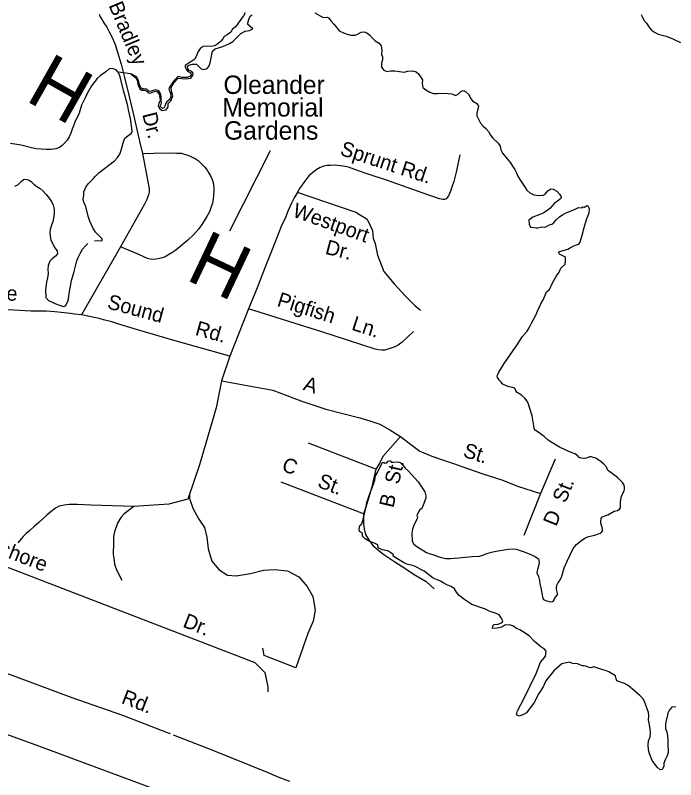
# Model space of a CAD drawing. Extents: x 1945482 to 2853149, y 66427 to 1015778.
# Drawn here: x 2352907 to 2355850, y 165984 to 169389 of the extents above; entities that cross this region are included whole.
import ezdxf

# ---------------------------------------------------------------- set-up
doc = ezdxf.new("R2010")
doc.units = 0
for name, color, linetype in [('Old_Level_10', 7, 'Continuous'), ('Old_Level_22', 7, 'Continuous'), ('Old_Level_35', 7, 'Continuous'), ('Old_Level_60', 7, 'Continuous')]:
    doc.layers.add(name, color=color, linetype=linetype)

msp = doc.modelspace()

# ---------------------------------------------------------------- linework, layer by layer
at = {"layer": 'Old_Level_22'}
msp.add_lwpolyline([(2354042.6, 168785.4), (2353861.4, 168427.5)], dxfattribs=at)
at = {"layer": 'Old_Level_35'}
for p, q in [((2353375.3, 168357.6), (2353201.2, 168054.7)), ((2353862.9, 167870.5), (2353825, 167761.2)), ((2354514.2, 167367.1), (2354213.3, 167482.8)), ((2355312.1, 167411.8), (2355247.9, 167258.2)), ((2355247.9, 167258.2), (2355172.6, 167071.1))]:
    msp.add_line(p, q, dxfattribs=at)
for points in [[(2353280.4, 169394.3), (2353284.8, 169382.3), (2353293.2, 169368.5), (2353302, 169355.1), (2353314.5, 169335.6), (2353325.5, 169316), (2353338.3, 169290.6), (2353351.7, 169258.9), (2353362.9, 169225.2), (2353379.1, 169172), (2353393.6, 169112.6), (2353412.5, 169033.2), (2353434, 168946.1), (2353460.6, 168829), (2353473, 168773.7)], [(2353473, 168773.7), (2353522.8, 168775.7), (2353598.9, 168776.4), (2353626.9, 168775.5), (2353646.9, 168774.4), (2353659.2, 168770.9), (2353675.5, 168765.6), (2353685.5, 168762.1), (2353697.9, 168756.3), (2353707.9, 168750.8), (2353722.4, 168741.6), (2353736.7, 168728), (2353751.5, 168712.5), (2353762.2, 168698.8), (2353768.5, 168689.2), (2353777, 168673.5), (2353783.8, 168657.7), (2353788.3, 168644.1), (2353791.1, 168622.2), (2353791.7, 168608.1), (2353790.7, 168584.1), (2353785.7, 168551.7), (2353776.8, 168527.4), (2353771.5, 168513.1), (2353760.1, 168493), (2353741.3, 168462), (2353724.3, 168437.4), (2353701.4, 168410.6), (2353676.4, 168387.6), (2353649.4, 168364.5), (2353622, 168343.4), (2353604.4, 168330.6), (2353586.8, 168320), (2353575.3, 168313.3), (2353563.3, 168308.9), (2353541.5, 168304.1), (2353525.5, 168301.5), (2353509.7, 168302.9), (2353495.5, 168306.2), (2353483.1, 168311.6), (2353456.7, 168322.8), (2353375.3, 168357.6)], [(2353473, 168773.7), (2353490.8, 168680.2), (2353503.2, 168616.7), (2353503.7, 168604.6), (2353503.8, 168600.6), (2353500.3, 168588.7), (2353491.1, 168566.3), (2353481.9, 168547.9), (2353375.3, 168357.6)], [(2354887.8, 168767.7), (2354870.9, 168690.9), (2354860.4, 168648.4), (2354850.4, 168618.8), (2354846, 168605.9), (2354837, 168585.5), (2354827.4, 168571), (2354819.6, 168568.7), (2354811.7, 168568.4), (2354797.5, 168571.8), (2354720.2, 168598.9), (2354566.1, 168652.9), (2354479, 168681.3), (2354436.4, 168695.7), (2354391.8, 168711.9), (2354367.7, 168716.9), (2354341.3, 168719.8), (2354327.5, 168721.2), (2354311.4, 168720.6), (2354297.3, 168720), (2354281.7, 168717.4), (2354265.8, 168710.9), (2354248.2, 168700.4), (2354230.7, 168687.5), (2354217, 168674.8), (2354199.8, 168654.1), (2354184.9, 168633.5), (2354173.4, 168617.3), (2354162.3, 168598.8), (2354149.1, 168576.3), (2354137.9, 168551.9), (2354123.4, 168519.2), (2354110.5, 168488.8), (2354092.1, 168448), (2354061.1, 168368.7), (2354024.6, 168279.3), (2353984.7, 168175.6), (2353946.4, 168081.9), (2353901.1, 167968.1), (2353862.9, 167870.5)], [(2354163.5, 168600.8), (2354424.1, 168512.5), (2354474.8, 168481.3), (2354498.2, 168430.6), (2354502.1, 168395.5), (2354509.9, 168372.1), (2354521.6, 168321.3), (2354548.9, 168247.2), (2354595.7, 168192.6), (2354646.3, 168138), (2354689.2, 168095.1), (2354712.6, 168075.6)], [(2353862.9, 167870.5), (2353619.9, 167939), (2353451.9, 167988.4), (2353368.9, 168013), (2353336.6, 168023.9), (2353300.2, 168032.3), (2353279.9, 168037.8), (2353257.8, 168042.8), (2353237.5, 168047.9), (2353201.2, 168054.7), (2353171.2, 168057.4), (2353153, 168060.6), (2353110.8, 168064.9), (2353082.8, 168067.7), (2353064.7, 168069.3), (2353044.6, 168070.4), (2352976.6, 168071.7), (2352848.4, 168078.4)], [(2354680.7, 167981), (2354630.8, 167933), (2354613.2, 167920.2), (2354597.5, 167911.7), (2354571.9, 167902.8), (2354554, 167897.8), (2354539.9, 167897.3), (2354526.1, 167899), (2354509.9, 167902.3), (2354272.8, 167978.9), (2353946.4, 168081.9)], [(2353825, 167761.2), (2353801.3, 167640.1), (2353728.1, 167386.6), (2353675.5, 167233.1)], [(2353825, 167761.2), (2354053.9, 167718.9), (2354179.4, 167671.4), (2354291, 167635.1), (2354366.3, 167615.6), (2354441.7, 167596), (2354486.7, 167582.4), (2354530.9, 167568.1), (2354575.6, 167543), (2354623, 167512.3)], [(2354623, 167512.3), (2354578.4, 167462), (2354544.9, 167422.9), (2354530.9, 167395), (2354514.2, 167367.1), (2354494.7, 167283.3), (2354477.9, 167227.5), (2354466.8, 167194), (2354458.8, 167167.5)], [(2354623, 167512.3), (2354667.6, 167478.8), (2354709.5, 167448.1), (2354762.5, 167425.7), (2354809.9, 167409), (2354860.1, 167392.2), (2354921.5, 167369.9), (2354994.1, 167344.8), (2355075, 167319.6), (2355144.7, 167291.7), (2355247.9, 167258.2)], [(2354458.8, 167167.5), (2354091.1, 167309.2)], [(2353683.1, 167254.2), (2353683.2, 167237.1), (2353698.6, 167194.1), (2353724.1, 167143.9), (2353749.5, 167106.7), (2353760.6, 167063.8), (2353766.9, 167012.9), (2353782.5, 166958.1), (2353814.6, 166919.2), (2353852.7, 166895.3), (2353890.8, 166892.1), (2353954.3, 166901.7), (2354013.1, 166917.6), (2354062.3, 166920.7), (2354119.5, 166914.4), (2354170.3, 166887.4), (2354206.8, 166844.5), (2354232.2, 166800), (2354243.3, 166739.6), (2354233.8, 166690.3), (2354210, 166634.7), (2354189.3, 166575.9), (2354156.5, 166482.1)], [(2353434.9, 167200.4), (2353244.8, 167207.5), (2353184.7, 167209.1), (2353146.9, 167209.5), (2353124.7, 167206.7), (2353102.9, 167201.9), (2353085.5, 167193), (2353066.1, 167178.4), (2353046.7, 167161.6), (2353031.2, 167146.9), (2353011.9, 167130), (2352990.6, 167111.4), (2352971.3, 167094.6), (2352955.8, 167079.9), (2352942.1, 167067.5), (2352917.9, 167038.6)], [(2353675.5, 167233.1), (2353591.1, 167210.7), (2353434.9, 167200.4)], [(2353434.9, 167200.4), (2353392.5, 167167.8), (2353376.8, 167151.3), (2353361.8, 167126.4), (2353356.1, 167109.3), (2353350.9, 167094.4), (2353346.1, 167075), (2353344.9, 167060.7), (2353344.2, 167042.2), (2353344, 167023), (2353342.6, 167003), (2353343.3, 166988.1), (2353346.4, 166969.3), (2353346.8, 166959.5), (2353349.4, 166943.5), (2353356.1, 166923.7), (2353362.6, 166909.9), (2353381.2, 166872)], [(2354458.8, 167167.5), (2354458.4, 167143.7), (2354458.4, 167124.2), (2354461.2, 167101.8), (2354466.8, 167076.7), (2354483.5, 167048.8), (2354500.2, 167026.5), (2354544.9, 166990.2), (2354597.9, 166953.9), (2354642.5, 166925.9), (2354684.4, 166898), (2354737.4, 166867.3), (2354773.7, 166833.8)], [(2352206.7, 166694.6), (2352263.7, 166828.2), (2352297, 166900.4), (2352338.6, 166964.3), (2352391.4, 167006), (2352452.5, 167019.9), (2352530.2, 167014.3), (2352655.2, 167000.4), (2352774.6, 166967.1), (2353974.1, 166505.9), (2354018.5, 166461.4), (2354032.4, 166397.5), (2354032.4, 166375.3)], [(2353598.4, 166187.9), (2353585, 166193.1), (2353386.1, 166269.3), (2353160.7, 166348.3), (2352908.9, 166442.4), (2352750.7, 166500.1), (2352564, 166564.6), (2352206.7, 166694.6), (2351847.3, 166826.4)], [(2351702.3, 166647.1), (2352243.1, 166411.9), (2352998.3, 166138.4)], [(2354156.5, 166482.1), (2354015.8, 166536.4), (2354010.2, 166569.8)], [(2354129.9, 165976.4), (2354101.6, 165985.5), (2354075, 165996.2), (2354030.2, 166016.4), (2353953.1, 166047.5), (2353784.4, 166114.7), (2353612.5, 166182.3)], [(2352998.3, 166138.4), (2353646.7, 165899.3)]]:
    msp.add_lwpolyline(points, dxfattribs=at)
at = {"layer": 'Old_Level_60'}
msp.add_line((2353421.2, 169128.7), (2353365.5, 169136.1), dxfattribs=at)
for points in [[(2353930.5, 169400.7), (2353923.5, 169386.2), (2353888, 169337.5), (2353874.2, 169326.7), (2353866.7, 169313.3), (2353851.5, 169302.1), (2353838, 169295.4), (2353831.2, 169284.1), (2353821.5, 169272.1), (2353809.5, 169262.4), (2353795.5, 169253.5), (2353777, 169250.3), (2353760.7, 169251.5), (2353744.2, 169250.6), (2353731, 169241.7), (2353721.5, 169228), (2353714.5, 169210.7), (2353706.5, 169194.1), (2353693.7, 169185.2), (2353677, 169175.1), (2353664.5, 169164.8), (2353663.7, 169158.8), (2353668.5, 169149.2), (2353673.5, 169140.3), (2353688.2, 169133.1), (2353691.2, 169125.1), (2353688.2, 169117.9), (2353672, 169112.1), (2353650.5, 169112.8), (2353634.2, 169117.2), (2353627.5, 169112.8), (2353616.7, 169099.9), (2353608.2, 169091.2), (2353601.2, 169079), (2353593.5, 169069.6), (2353591.2, 169059.5), (2353599, 169042.9), (2353599.7, 169029.2), (2353596.7, 169019.1), (2353590.5, 169011.2), (2353582, 169004), (2353577.5, 168998.2), (2353574.2, 168988.1), (2353569.7, 168977.3), (2353563.5, 168974.4), (2353552.7, 168984.5), (2353558.2, 168996.7), (2353556.7, 169011.9), (2353557.5, 169027), (2353554.2, 169041.5), (2353546, 169052.3), (2353532, 169057.3), (2353520.5, 169054.4), (2353512.7, 169051.6), (2353503.5, 169050.1), (2353493.5, 169059.5), (2353478.2, 169061.7), (2353472, 169060.9), (2353466.7, 169066), (2353460.5, 169080.4), (2353456, 169098.4), (2353447.5, 169115), (2353421.2, 169128.7), (2353444.2, 169110), (2353450.5, 169099.9), (2353452.7, 169082.6), (2353455.2, 169075.3), (2353461.2, 169060.9), (2353469.7, 169055.9), (2353486.7, 169055.9), (2353495.2, 169049.4), (2353501.2, 169043.6), (2353508.2, 169042.2), (2353522, 169048.7), (2353531.2, 169050.8), (2353539, 169047.9), (2353547.5, 169037.8), (2353550.5, 169022), (2353552, 169009.7), (2353546, 168996.7), (2353544.2, 168983.8), (2353550.5, 168972.9), (2353561.2, 168965), (2353579, 168968.6), (2353588.2, 168981.6), (2353588.2, 168996), (2353601.2, 169009.7), (2353608.2, 169029.9), (2353604.2, 169046.5), (2353601.2, 169062.4), (2353602.7, 169071), (2353615, 169090.5), (2353632.7, 169108.5), (2353665.7, 169105.6), (2353689.7, 169109.2), (2353697.5, 169120.8), (2353699.7, 169130.2), (2353694.2, 169138.1)], [(2353694.2, 169138.1), (2353681.2, 169142.8), (2353675.7, 169150.1), (2353674.2, 169162.1), (2353680.7, 169167.3), (2353696, 169171.1), (2353714, 169171.2), (2353735.2, 169150), (2353747.2, 169147.2), (2353761.7, 169151.5), (2353770, 169161.6), (2353775.2, 169177.2), (2353785.2, 169229.8), (2353798.2, 169240), (2353831.2, 169249.8), (2353861.7, 169263.9), (2353876, 169272.1), (2353888.2, 169283.6), (2353899.5, 169296.7), (2353912, 169308.8), (2353930.7, 169317.8), (2353950, 169321.8), (2353966, 169328.2), (2353943.5, 169348.1), (2353942.7, 169356.1), (2353947.2, 169370.5), (2353953.2, 169385.3), (2353961.7, 169391.5)], [(2354242.2, 169399.8), (2354278.5, 169380.1), (2354296.2, 169380.5), (2354302, 169377.8), (2354313.7, 169362.4), (2354326.5, 169349.7), (2354336.5, 169337.6), (2354350, 169319.6), (2354369, 169310.6), (2354385.7, 169304.4), (2354402.2, 169300.8)], [(2355695.2, 169392.9), (2355701, 169383.6), (2355708, 169366.9), (2355719.2, 169353.7), (2355730.5, 169337.8), (2355742.5, 169323.5), (2355755.5, 169314.5), (2355772.2, 169305.5), (2355789.5, 169300.2), (2355807.5, 169295.8), (2355839.7, 169282.6), (2355870.5, 169268)], [(2354402.2, 169300.8), (2354421.2, 169301), (2354435, 169307), (2354448.5, 169314.2), (2354461.7, 169315.8), (2354473, 169311.4), (2354484.7, 169301.6), (2354497, 169288.7), (2354511, 169275.7), (2354528, 169264.6), (2354537.5, 169253.5), (2354540, 169232.7), (2354538.5, 169213.8), (2354543, 169204.6), (2354543.2, 169191.3), (2354538.5, 169175.2), (2354538.2, 169158), (2354549.5, 169144.6), (2354563, 169139.5), (2354578.7, 169141.4), (2354597.5, 169142), (2354640, 169136.5), (2354656, 169140.2), (2354677.7, 169142.2), (2354692.7, 169137.5), (2354704.2, 169128.5), (2354722, 169102.2), (2354720.7, 169085), (2354722.7, 169067.5), (2354736.5, 169056.4), (2354753.5, 169047), (2354771, 169041.2), (2354788, 169040.7), (2354818.5, 169042.4), (2354835.7, 169041.4), (2354851.7, 169038.8), (2354869, 169032), (2354880, 169037.9), (2354891.7, 169049.5), (2354902.5, 169054.4), (2354914, 169048.4), (2354927.7, 169036.3), (2354937.2, 169016.8), (2354946.2, 169006.8), (2354964, 168995.8), (2354971.5, 168984.5), (2354963, 168953.3), (2354963.7, 168940.6), (2354979.5, 168908.8), (2354991.7, 168895.7), (2355004, 168885), (2355015, 168871.5), (2355024, 168854.6), (2355034.2, 168841.7), (2355058, 168820.2), (2355067.2, 168806.8), (2355071.2, 168789.4), (2355077.5, 168774.6), (2355113.5, 168732.3), (2355123.2, 168717.6), (2355133, 168702.3), (2355140.7, 168688), (2355146.7, 168673.1), (2355154.7, 168657.4), (2355163.5, 168643.8), (2355176.5, 168626), (2355186.7, 168609.6), (2355200, 168598.5), (2355217.5, 168589), (2355239.7, 168586.8), (2355259.5, 168587.3), (2355268, 168592.5), (2355280.5, 168607.3), (2355293.5, 168616.7), (2355304.2, 168614.9), (2355320, 168605.2), (2355331.7, 168592.1), (2355339, 168580.9), (2355337.2, 168572.8), (2355322.5, 168561.1), (2355309.7, 168552.9), (2355289.5, 168527.8), (2355276, 168517.6), (2355259.7, 168508), (2355245, 168501.4), (2355213.2, 168489.2), (2355196, 168476.6), (2355197.5, 168459.4), (2355203.2, 168445.4), (2355219, 168444.4), (2355228.2, 168441.6), (2355236, 168441.9), (2355252.7, 168446.6), (2355265.2, 168444.6), (2355270.7, 168446.5), (2355287, 168455.6), (2355302.5, 168459.8), (2355319.2, 168479.6), (2355332.7, 168491.7), (2355346.5, 168501.8)], [(2353260, 168384.3), (2353276.5, 168385.4), (2353292, 168384.1), (2353294.8, 168385.9), (2353292.5, 168394.3), (2353278.3, 168409.9), (2353264.3, 168423.3), (2353253.3, 168439.3), (2353238.8, 168471.5), (2353232.8, 168489.7), (2353219.5, 168542.5), (2353211.8, 168555.7), (2353208.8, 168570.5), (2353211.8, 168586.5), (2353212.5, 168602), (2353221.3, 168623.2), (2353231, 168638.8), (2353253.5, 168661.2), (2353263.8, 168672.5), (2353279.3, 168687.6), (2353348.3, 168740.1), (2353362.3, 168755.2), (2353372.5, 168771.1), (2353378.5, 168788.3), (2353388.5, 168825.6), (2353395.5, 168842.3), (2353408.3, 168852.9), (2353422.8, 168862.7), (2353427, 168869.8), (2353426.5, 168886.1), (2353420, 168930), (2353411.5, 168967.6), (2353408.3, 168986.5), (2353389.3, 169054.5), (2353378.8, 169097.7), (2353372.5, 169119.1), (2353365.5, 169136.1), (2353356.3, 169145.9), (2353339, 169151.5), (2353324.8, 169150.4), (2353310, 169137.7), (2353284.5, 169119.2), (2353272, 169107.1), (2353247, 169074.2), (2353227, 169040.4), (2353218, 169022), (2353202.3, 168988.4), (2353191.5, 168953.6), (2353184, 168936.8), (2353173, 168917.1), (2353165.8, 168896.3), (2353159.5, 168882), (2353153.8, 168864.2), (2353146.5, 168847.8), (2353138.5, 168833.4), (2353126.5, 168819.4), (2353115.5, 168808.7), (2353104, 168800.2), (2353087.3, 168794.4), (2353066, 168791.1), (2353044, 168790.8), (2352999.3, 168794.6), (2352978.8, 168798.2), (2352932.3, 168810.5), (2352885, 168818.1)], [(2352905.2, 168628.6), (2352918.5, 168633.3), (2352933.5, 168648.7), (2352943.5, 168657.1), (2352951, 168659.4), (2352966, 168656.1), (2352979.2, 168648), (2352990, 168637.3), (2353002.2, 168626.9), (2353017.2, 168617.1), (2353031, 168605.4), (2353044.5, 168591.4), (2353057.5, 168574.9), (2353068, 168559.9), (2353076.2, 168543.2), (2353080.7, 168524.9), (2353080.7, 168505.7), (2353077, 168485.2), (2353073.5, 168468.9), (2353067.5, 168454.4), (2353062.7, 168435.6), (2353060.7, 168419.7), (2353062, 168403.6), (2353065.5, 168388.2), (2353081, 168355.4), (2353093.2, 168339.3), (2353095.5, 168326.5), (2353086.2, 168315.7), (2353072.5, 168305.5), (2353060.7, 168294.4), (2353053.5, 168273.9), (2353052.2, 168256.9), (2353053, 168239.1), (2353049.7, 168219.6), (2353045.5, 168200.2), (2353041.5, 168166.4), (2353042.2, 168132.7), (2353054.2, 168118.9), (2353087.5, 168103.9), (2353103.7, 168097.5), (2353122, 168091.5), (2353131, 168095.3), (2353139, 168110.5), (2353144, 168124.7), (2353145.7, 168141.4), (2353156.7, 168208.1), (2353167.2, 168241.3), (2353181.5, 168295.7), (2353187, 168310.3), (2353196.5, 168328.6), (2353207, 168346.6), (2353218, 168360.7), (2353230, 168372.3)], [(2355346.5, 168501.8), (2355364.2, 168511.2), (2355399.5, 168524.2), (2355416.2, 168532.4), (2355433, 168531.2), (2355436.5, 168535.2), (2355443.5, 168534.9), (2355453.5, 168542.4), (2355457.7, 168540.3)], [(2355417.7, 168370), (2355423.5, 168378.2), (2355433.7, 168410.1), (2355441.7, 168443.8), (2355452, 168479.1), (2355463.5, 168509.1), (2355466.2, 168526.3), (2355460.2, 168538.9), (2355457.7, 168540.3)], [(2355504, 167078.5), (2355514, 167081.6), (2355516.7, 167084.4), (2355520.7, 167087.4), (2355523, 167092.9), (2355524.2, 167099.7), (2355522.7, 167106.8), (2355516.7, 167126.5), (2355515.5, 167136.1), (2355518.2, 167146.8), (2355520.2, 167152), (2355522.7, 167154.5), (2355546.7, 167164.3), (2355575.2, 167179.8), (2355590.7, 167183), (2355600.2, 167190), (2355603.5, 167195.2), (2355603.5, 167220.5), (2355606.5, 167241.5), (2355611.2, 167254.9), (2355620, 167271), (2355621.5, 167278.8), (2355621.5, 167288.6), (2355618.5, 167299), (2355612.2, 167308.2), (2355602.7, 167318.3), (2355590.2, 167329.9), (2355549.7, 167359.3), (2355546, 167364.8), (2355542.5, 167375), (2355530.2, 167388.8), (2355517.7, 167400.1), (2355494.2, 167415.7), (2355488.2, 167418.1), (2355482.5, 167419.7), (2355474.5, 167422.4), (2355466.7, 167421.5), (2355455.5, 167418.3), (2355445.2, 167414.8), (2355428.5, 167416.6), (2355420, 167419.6), (2355419.5, 167419.7), (2355411.5, 167427.9), (2355400.2, 167435.1), (2355373.2, 167446.3), (2355332.7, 167465.9), (2355298.5, 167485.6), (2355282, 167496.8), (2355264, 167512.2), (2355226.5, 167538.9), (2355223.2, 167541.6), (2355219.7, 167547.7), (2355217, 167559.9), (2355210.2, 167604.8), (2355193.7, 167656.7), (2355187.7, 167670.8), (2355177.2, 167683.4), (2355163, 167696.5), (2355142.7, 167708.6), (2355137.7, 167715.8), (2355133.7, 167725.5), (2355130.7, 167728.4), (2355123.2, 167730.5), (2355101, 167736), (2355080, 167746.5), (2355070.2, 167755.6), (2355064, 167762.7), (2355055.7, 167776.3), (2355054.2, 167782.3), (2355056.5, 167788.4), (2355062, 167800), (2355073.2, 167818.4), (2355085.5, 167837.5), (2355146.7, 167925.2), (2355165, 167957), (2355187.2, 167981.4), (2355197.5, 167996.9), (2355206.5, 168018.2), (2355226.5, 168053), (2355234.5, 168071), (2355241, 168088), (2355249, 168104.1), (2355259.2, 168121.4), (2355268.7, 168142), (2355274, 168157.3), (2355287.7, 168167.1), (2355301.5, 168196.9), (2355318.5, 168228.1), (2355330.5, 168245.1), (2355338, 168262.5), (2355357.7, 168280.8), (2355359.2, 168296.1), (2355358, 168311.7), (2355332, 168324.8), (2355327, 168333.6), (2355332.5, 168337.6), (2355368.5, 168347.5), (2355383.7, 168355.7), (2355402.5, 168364.5), (2355417.7, 168370)], [(2355262.7, 166566.8), (2355249.5, 166576.1), (2355220.7, 166599), (2355198.5, 166622.7), (2355170.5, 166642.2), (2355154.5, 166651.2), (2355140.5, 166657.9), (2355124, 166668.9), (2355108, 166674.2), (2355088.2, 166672.1), (2355075.2, 166664), (2355054, 166659.4), (2355032.7, 166656.7), (2355035, 166669.7), (2355041.5, 166674.5), (2355059, 166677.4), (2355076, 166683.8), (2355079.7, 166691.6), (2355072, 166704.9), (2355063.2, 166717.8), (2355047.2, 166725.2), (2355031, 166729.6), (2355015, 166735.5), (2355002.2, 166743.3), (2354980.5, 166751.6), (2354959, 166758.2), (2354941.2, 166764.9), (2354909.7, 166785.4), (2354884.2, 166804.7), (2354873.5, 166819.3), (2354864, 166834), (2354849.7, 166844.2), (2354832.5, 166851), (2354817, 166858.9), (2354801.5, 166868.8), (2354783.5, 166875.4), (2354769.2, 166882.3), (2354728.2, 166913), (2354682.5, 166936.1), (2354652, 166944.1), (2354637, 166951.1), (2354621.7, 166960.6), (2354606.7, 166968.7), (2354591.2, 166979), (2354592.5, 166985.7), (2354580.5, 166994.8), (2354566.5, 167003.4), (2354541.2, 167007.9), (2354524, 167016.2), (2354522.2, 167030), (2354514.2, 167034.8), (2354481.2, 167047.8), (2354466.2, 167057.5), (2354453.5, 167068.3), (2354453.5, 167082.7), (2354441, 167089.4), (2354439.5, 167100), (2354441.5, 167115.9), (2354446.7, 167117.4), (2354450.7, 167124.4), (2354455.7, 167139.1), (2354467.2, 167186.4), (2354474, 167218.6), (2354484, 167249.9), (2354503.7, 167300.2), (2354509.7, 167317.8), (2354510.2, 167328.5), (2354512.5, 167338.1), (2354520.5, 167351.9), (2354526.2, 167365.9), (2354543, 167396.3), (2354547.5, 167399), (2354550.2, 167393.6), (2354562, 167395.5), (2354568, 167402.6), (2354578.2, 167405.1), (2354582, 167398.5), (2354592, 167397.9), (2354612, 167399.2), (2354621.2, 167396.6), (2354634.5, 167384.8), (2354644.2, 167372.4), (2354657.7, 167359.9), (2354701.7, 167310.3), (2354731.7, 167265.7), (2354736.5, 167248.6), (2354735.7, 167237.7), (2354724.2, 167207.4), (2354716.5, 167189.5), (2354711.5, 167189.1), (2354703.5, 167177.5), (2354696.2, 167160.8), (2354698.7, 167153.1), (2354697, 167147.3), (2354682.7, 167116.6), (2354676.5, 167099.5), (2354674.5, 167082.4), (2354675, 167046.9), (2354682.7, 167033.8), (2354696.7, 167023.4)], [(2354696.7, 167023.4), (2354739.7, 166996.6), (2354755.5, 166990.4), (2354772, 166985.4), (2354790.5, 166978.4), (2354806, 166973.6), (2354824.2, 166969.5), (2354845.7, 166968.9), (2354862.5, 166970.9), (2354883.7, 166972), (2354943.5, 166978.2), (2354976, 166979.9), (2354990.5, 166984.2), (2355008.5, 166991.5), (2355028.5, 166997.4), (2355049.5, 167002.6), (2355103.5, 167011.5), (2355121.7, 167012.1), (2355138.7, 167010.1), (2355174, 166999.2), (2355207.2, 166986.2), (2355224.2, 166977.5), (2355238.7, 166967.6), (2355240.7, 166952.1), (2355238.2, 166935.7), (2355233.5, 166920.9), (2355231.5, 166905.2), (2355238, 166889.1), (2355242.5, 166871.5), (2355244.2, 166856.3), (2355249, 166838.9), (2355257, 166791.6), (2355260.7, 166786.5), (2355269.7, 166781.8), (2355292, 166775.9), (2355301.5, 166777.2), (2355306.5, 166781.8), (2355309, 166791.2), (2355320.7, 166803.8), (2355322.5, 166807.5), (2355322.7, 166813.9), (2355320.7, 166824.9), (2355319.2, 166836.9), (2355320.7, 166850.1), (2355324.7, 166859.2), (2355333.7, 166871.2), (2355341.7, 166890.8), (2355352.2, 166927.3), (2355365.7, 166958.1), (2355392.7, 167014.2), (2355407.5, 167032.3), (2355425.5, 167046.5), (2355444.5, 167059.8), (2355461.5, 167067.6), (2355490, 167073.2), (2355504, 167078.5)], [(2355850, 166309), (2355833.2, 166306.8), (2355822.2, 166295.4), (2355814, 166280.4), (2355811.5, 166264.1), (2355807.2, 166248.7), (2355804.5, 166231.2), (2355804.7, 166211), (2355810, 166197), (2355813.7, 166177.5), (2355815, 166162), (2355814.2, 166144.8), (2355815.7, 166105.2), (2355812.2, 166090.1), (2355803, 166072.6), (2355797, 166057.7), (2355796.7, 166042.3), (2355789.5, 166029.3), (2355780.2, 166028.1), (2355767.2, 166039.5), (2355745.5, 166068.6), (2355731.7, 166103.1), (2355728.7, 166118.5), (2355727.2, 166137.4), (2355728.5, 166156.7), (2355735.5, 166174.7), (2355737.2, 166192), (2355736.2, 166211.5), (2355728.7, 166250.4), (2355729.7, 166268.4), (2355728.5, 166283.7), (2355710.2, 166332), (2355703.5, 166345.5), (2355691.2, 166357.8), (2355647.5, 166395.5), (2355634.5, 166405.1), (2355621, 166412.9), (2355587.5, 166424.5), (2355584.5, 166432.8), (2355582, 166446), (2355551.5, 166464.8), (2355536.7, 166470.3), (2355520.7, 166474.7), (2355485.7, 166487), (2355471.2, 166481.7), (2355460.2, 166485), (2355450, 166489.1), (2355439.7, 166491.3), (2355435, 166491.7), (2355411.7, 166500.6), (2355391.7, 166501.2), (2355375.7, 166508.1), (2355342.5, 166500.3), (2355306.7, 166469), (2355271, 166424.6), (2355259.5, 166397.2), (2355239.7, 166367.6), (2355219.2, 166327.3), (2355184.5, 166281.3), (2355171.2, 166273.8), (2355152.2, 166267.1), (2355140.7, 166272.1), (2355145, 166290.5), (2355174.7, 166346.6), (2355228.5, 166457.1), (2355247, 166507.9), (2355266.5, 166529.5), (2355270, 166533.8), (2355272.2, 166556.3), (2355270.2, 166559.7), (2355266, 166563.4), (2355262.7, 166566.8)]]:
    msp.add_lwpolyline(points, dxfattribs=at)

# ---------------------------------------------------------------- texts
at = {"layer": 'Old_Level_10'}
for s, height, rotation, p in [('Bradley', 65.62, 292.6508, (2353321.7, 169434.1)), ('Dr.', 65.62, 284.3075, (2353471.9, 168948.3)), ('Sprunt Rd.', 65.62, 341.8753, (2354350.1, 168768.3)), ('Westport', 65.62, 340.3196, (2354138.1, 168493.9)), ('Dr.', 65.62, 345.7956, (2354284.4, 168327.2)), ('Greenville', 65.62, 357.8312, (2352520.6, 168131.7)), ('Sound', 65.62, 344.7577, (2353312.6, 168084.5)), ('Pigfish', 65.62, 342.4956, (2354069.2, 168094.8)), ('Rd.', 65.62, 344.2562, (2353704.8, 167966.2)), ('Ln.', 65.62, 342.0907, (2354401.4, 167989.1)), ('A', 65.6, 341.9826, (2354185.7, 167721.1)), ('St.', 65.62, 342.746, (2354898.4, 167423.4)), ('C', 65.6, 338.914, (2354089.9, 167362.4)), ('B  St.', 65.62, 76.8759, (2354591.3, 167192)), ('St.', 65.62, 338.914, (2354249.6, 167289.4)), (' D  St.', 65.62, 68.0667, (2355308.1, 167086.3)), ('Parkshore', 65.62, 338.5295, (2352662.9, 167055)), ('Dr.', 65.62, 338.3725, (2353649.4, 166666.3)), ('Rd.', 65.62, 339.0574, (2353375.5, 166326))]:
    msp.add_text(s, height=height, rotation=rotation, dxfattribs=at).set_placement(p)
at = {"layer": 'Old_Level_22'}
for rotation, p in [(330.5507, (2352945.9, 169012.6)), (334.6788, (2353660, 168214.4))]:
    msp.add_text('H', height=246.1, rotation=rotation, dxfattribs=at).set_placement(p)
for s, p in [('Oleander', (2353834.7, 169038.9)), ('Memorial', (2353829.7, 168938)), ('Gardens', (2353836.7, 168835.2))]:
    msp.add_text(s, height=82.02, dxfattribs=at).set_placement(p)

doc.saveas('drawing.dxf')
